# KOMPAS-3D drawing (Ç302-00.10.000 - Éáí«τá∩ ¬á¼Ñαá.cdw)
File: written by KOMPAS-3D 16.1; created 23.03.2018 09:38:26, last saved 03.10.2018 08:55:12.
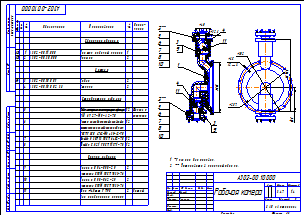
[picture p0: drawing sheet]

Sheet 1: A3, landscape

Title block, sheet 1: name: Рабочая камера; designation: А302-00.10.000; mass: 3,47; scale: 1:4; sheets: 1; organisation: ЗАО «Астерион»; sheet format: A3; stored path: Z:\Мембранные насосы\Мембранный электропривод\А302-00.00.000 - ASTRA-302 (МЭ200)\Чертежи\А302-00.10.000 - Рабочая камера.cdw; drawn by: Милов; technical control: Лучихин

Views: Вид 1, Местный разрез 1, Вид:1, Проекционный вид 2
Referenced files in Z:\1 ПКИ 3D\Полипропиленовые фитинги, трубы\: Колено 45гр 40 FV PPR ф. FV PLAST.m3d, Труба ф40х3,7 (PN10) FV PPR ф. FV PLAST.m3d, Колено 90гр 40 FV PPR ф. FV PLAST.m3d
Referenced files in Z:\Мембранные насосы\Мембранный электропривод\А302-00.00.000 - ASTRA-302 (МЭ200)\3Д\: А302-00.10.001 - Седло.m3d, А302-00.31.001 - Корпус.m3d, А302-00.30.001 - Прижим.m3d, А302-00.12.001 - Крышка.m3d, А302-00.10.002 3Д - Стакан.m3d, А302-00.10.000 - Рабочая камера.a3d, А302-00.12.000 - Крышка.a3d, А302-00.11.001 - Колена 45гр ф40.m3d, А302-00.31.000 - Корпус.a3d, А302-00.11.000 - Крышка рабочей камеры.a3d, А302-00.30.000 - Прижим.a3d
Referenced files in Z:\1 ПКИ 3D\РТИ\Кольца ГОСТ 9833-76\: Кольцо 054-058-25 EPDM ГОСТ 9833-76.m3d, Кольцо 058-062-25 EPDM ГОСТ 9833-76.m3d
Referenced files in Z:\Мембранные насосы\Мембранный электропривод\А302-00.00.000 - ASTRA-302 (МЭ200)\Чертежи\: А302-00.11.000 - Крышка рабочей камеры.cdw, А302-00.10.001 - Седло.cdw, А302-00.30.000 - Прижим.cdw
Referenced files: graphic.tdp
Referenced files in Z:\1 ПКИ 3D\2 Китай\: Шар PTFE ф45.m3d
Referenced files in D:\МЭ200\Макеты\: Заготовка стакан.m3d
Referenced files in C:\Program Files\ASCON\KOMPAS-3D V16\Libs\PartLib\DATA\vault\Methods\Kompas\3D\: PLib_Washer_1_712.m3d, PLib_Washer_2_712.m3d, PLib_Nut_ISO_1100.m3d, PLib_Screw_DIN_7984_1500.m3d
Referenced files in Z:\2 Стандартные изделия 3D\Гайки\DIN 6927\: Гайка шестигранная самостопорящаяся с фланцем DIN 6927-M5 - A2-70.m3d
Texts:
  *Размеры для справок.
  ** Установить в конечной сборке.
  Крышка рабочей камеры
  Седло
  Шар  45mm PTFE
  для мембранного насоса
  Шар @2~45mm PTFE / для мембранного насоса
  Китай
  Стакан
  Прижим
  Шайба C.5.21 ГОСТ 11371-78
  Крепежное изделие ГОСТ
  Шайба
  ГОСТ
  Сталь 12Х18Н10Т ГОСТ 5632-72
  Шайба 5 30Х13 ГОСТ 6402-70
  Сталь 30Х13 ГОСТ 5632-72
  Гайка шестигранная самостопорящаяся с фланцем
  DIN 6927-M5-A2-70
  Гайка
  шестигранная
  самостопорящаяся
  фланцем
  DIN
  Фланец с
  насечками
  Фланец снасечками
  Винт с цилиндрической головкой и
  шестигранным углублением под ключ
  ГОСТ Р ИСО  4762-М5 x 35-A2-70
  Винт с цилиндрической головкой и шестигранным углублением под ключ
  Р ИСО
  Нержавеющая сталь
  Винт с цилиндрической головкой и шестигранным углублением под ключ ГОСТ Р ИСО  4762-М5 x 35-A2-70
  Кольцо 054-058-25
  материал EPDM ГОСТ 9833-76
  Кольцо 054-058-25 / материал EPDM ГОСТ 9833-76
  Кольцо 058-062-25
  Кольцо 058-062-25 / материал EPDM ГОСТ 9833-76
  Лит-Масса-Масштаб
  Материал-Предприятие
  Title Specification
  Body Specification ( left align )
  Body Specificaton ( centered )
  Поз.
  Кол.
  Приме-
  чание
  Таблица спецификации
  Крышка
  Труба ф40х3,7 (PN10) FV PPR ф. FV PLAST
  Колено 45гр 40 FV PPR ф. FV PLAST
  Колено 45гр ф40
  Корпус
  Колено 90гр 40 FV PPR ф. FV PLAST
  Шар PTFE ф45
  Гайка шестигранная с фланцем ГОСТ Р ИСО 4161 - M5 - A2-70
  Гайка шестигранная самостопорящаяся с фланцем DIN 6927-M5 - A2-70
  Винт с цилиндрической головкой и шестигранным углублением под ключ ГОСТ Р ИСО 4762 - М5 x 35 - A2-70
  Кольцо 054-058-25 EPDM
  Кольцо 058-062-25 EPDM
Dimensions and other numbers on the sheet: 1; 2**; 5; 6; 7; 8; 10; 3; 9; 11; 4; 40; 32,6; 280; 287; 397,31; 135; 302; 6,5; 12 отв.; 2; 21; 40Х; 019; 58; 30Х13; 1:4; 3,47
